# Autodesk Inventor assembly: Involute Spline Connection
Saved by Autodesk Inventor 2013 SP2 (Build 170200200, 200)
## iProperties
Created: 2020-02
Part Number: Involute Spline Connection
Document SubType Name: Assembly
Designer: DELL
ClientObjectVersion: 1
Author: DELL
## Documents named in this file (1)
- C:\Users\DELL\Dropbox\Inventor\Projects\Quadcopter F450\Assemblies\Servo Accelerator Spline Makeup\Design Accelerator\Involute Spline Connection1.iam
